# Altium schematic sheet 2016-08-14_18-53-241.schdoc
size 349 x 134 mm; SheetNumber: 1; SheetTotal: 1
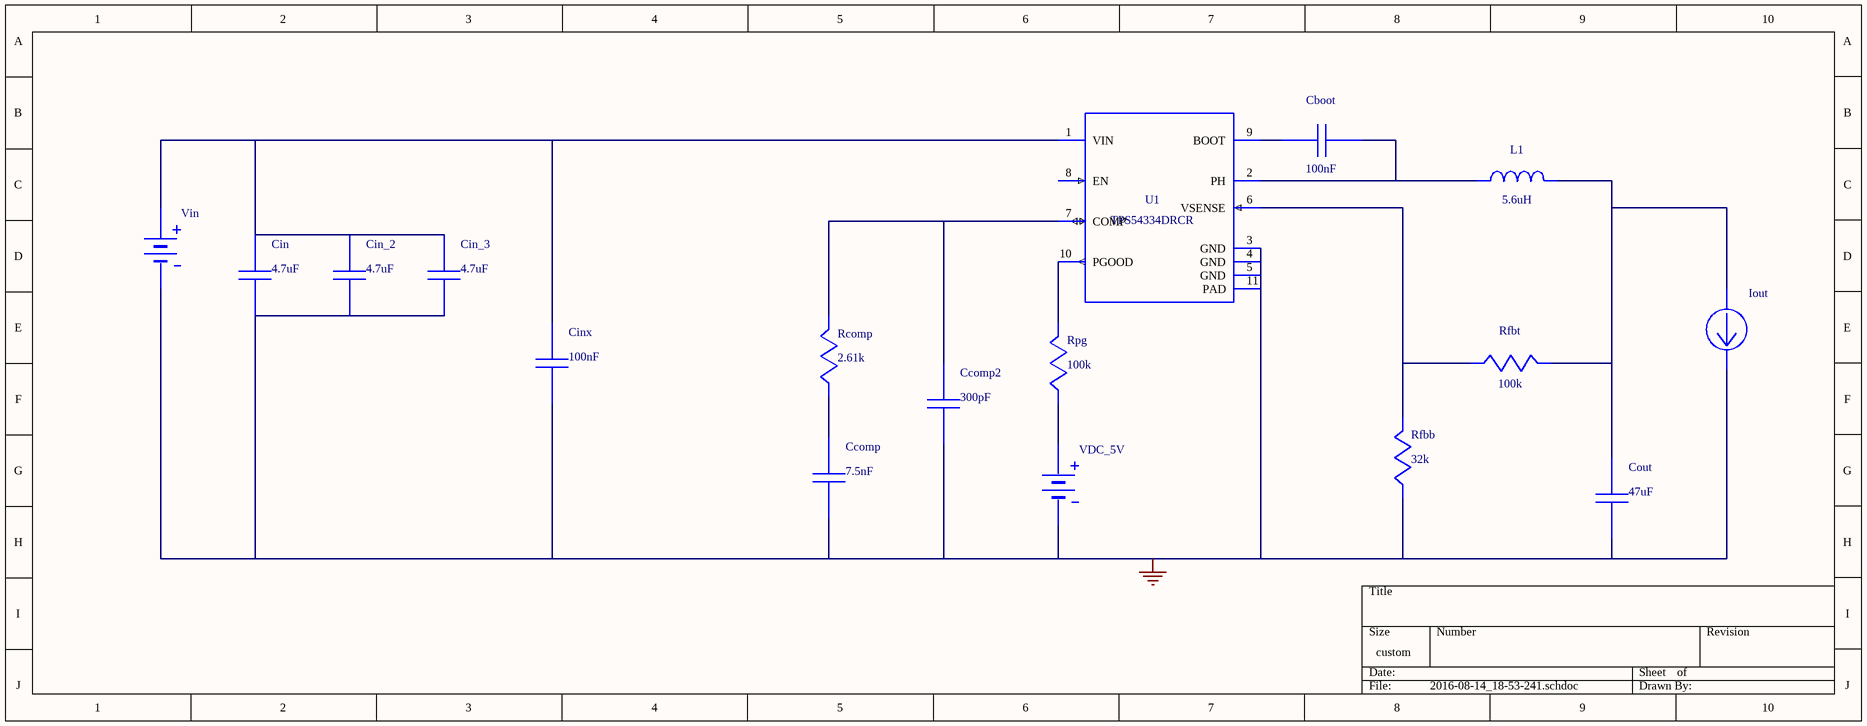
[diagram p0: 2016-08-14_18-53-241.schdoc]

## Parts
Cboot  value 100nF  (hidden comment: C0805C104K5RACTU)
Ccomp  value 7.5nF  (hidden comment: GRM2195C1H752JA01D)
Ccomp2  value 300pF  (hidden comment: GRM1555C1H301GA01D)
Cin  value 4.7uF  (hidden comment: GRM31CR71H475KA12L)
Cin_2  value 4.7uF  (hidden comment: GRM31CR71H475KA12L)
Cin_3  value 4.7uF  (hidden comment: GRM31CR71H475KA12L)
Cinx  value 100nF  (hidden comment: C0805C104K5RACTU)
Cout  value 47uF  (hidden comment: GRM31CC80J476KE18L)
Iout  WB_CURRENT_LOAD  (value not drawn)
L1  value 5.6uH  (hidden comment: SRP7030-5R6FM)
Rcomp  value 2.61k  (hidden comment: CRCW04022K61FKED)
Rfbb  value 32k  (hidden comment: RT0805BRD0732KL)
Rfbt  value 100k  (hidden comment: CRCW0402100KFKED)
Rpg  value 100k  (hidden comment: CRCW0402100KFKED)
U1  TPS54334DRCR
VDC_5V  WB_PRIM_DC_VOLTAGE_SOURCE  (value not drawn)
Vin  WB_BATTERY  (value not drawn)

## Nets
0: Ccomp.2 Ccomp2.2 Cin.2 Cin_2.2 Cin_3.2 Cinx.2 Cout.2 Iout.2(-) Rfbb.2 U1.3(GND) U1.4(GND) U1.5(GND) U1.11(PAD) VDC_5V.2(-) Vin.2(-)
NetCboot_1: Cboot.1 U1.9(BOOT)
NetCboot_2: Cboot.2 L1.1 U1.2(PH)
NetCcomp2_1: Ccomp2.1 Rcomp.1 U1.7(COMP)
NetCcomp_1: Ccomp.1 Rcomp.2
NetCin_1: Cin.1 Cin_2.1 Cin_3.1 Cinx.1 U1.1(VIN) Vin.1(+)
NetCout_1: Cout.1 Iout.1(+) L1.2 Rfbt.1
NetRfbb_1: Rfbb.1 Rfbt.2 U1.6(VSENSE)
NetRpg_1: Rpg.1 U1.10(PGOOD)
NetRpg_2: Rpg.2 VDC_5V.1(+)

Not connected (* = marked no-connect by the designer): U1 8(EN)

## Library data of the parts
Cboot Cinx = C0805C104K5RACTU: Manufacturer Name: Kemet
Ccomp = GRM2195C1H752JA01D: GRM2195C1H752JA0; Manufacturer Name: MuRata
Ccomp2 = GRM1555C1H301GA01D: GRM1555C1H301GA0; Manufacturer Name: MuRata
Cin Cin_2 Cin_3 = GRM31CR71H475KA12L: GRM31CR71H475KA1; Manufacturer Name: MuRata
Cout = GRM31CC80J476KE18L: GRM31CC80J476KE1; Manufacturer Name: MuRata
L1 = SRP7030-5R6FM: Manufacturer Name: Bourns
Rcomp = CRCW04022K61FKED: Manufacturer Name: Vishay-Dale
Rfbb = RT0805BRD0732KL: Manufacturer Name: Yageo America
Rfbt Rpg = CRCW0402100KFKED: Manufacturer Name: Vishay-Dale
U1 = TPS54334DRCR: Manufacturer Name: Texas Instruments
VDC_5V = WB_PRIM_DC_VOLTAGE_SOURCE: WB_PRIM_DC_VOLTA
